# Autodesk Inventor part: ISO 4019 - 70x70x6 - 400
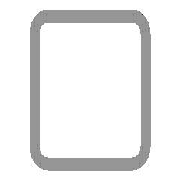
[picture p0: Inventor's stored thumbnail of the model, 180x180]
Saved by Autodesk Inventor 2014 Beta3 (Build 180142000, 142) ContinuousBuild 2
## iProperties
IsCustomPart: 1
Created: 2010-11
Part Number: ISO 4019 - 70x70x6 - 400
Material: Steel, Mild
Description: Structural steels - Cold-formed, welded, structural hollow sections
Document SubType Name: Modeling
Standard: ISO
Designer: Beta-8540w
Standard Revision: Second edition 2001-09-01
Standards Organization: ISO
Language: en-US
Size Designation: 70x70x6
Categories: <MemberInstance><Categories><Category DisplayName="Structural Shapes" InternalName="089c4875-fa83-4c05-b084-43b9cc11f5ed" Mnemonic="GRDR"><CategoryParameter Dis
Stock Number: 70x70x6
Density: 7.86 g/cm^3
Appearance: Steel
_CCFamilyMember: 28
_CCFamilyDisplayName: ISO 4019 (Square) - Structural steels - Cold-formed, welded, structural hollow sections
_FrameMemberDoc: Frame Member File
_Version: 15.0.0
_GetPNFromCC: 1
G_L: 400.000 mm
G_W: 70.000 mm
G_H: 70.000 mm
Author: Beta-8540w
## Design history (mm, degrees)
node "Start plane"
node "End plane"
sketch "Sketch"
  geometry: L1 (-35, -23)-(-35, 23); L2 (-23, 35)-(23, 35); L3 (35, 23)-(35, -23); L4 (23, -35)-(-23, -35); L5 (-23, 29)-(23, 29); L6 (29, 23)-(29, -23); L7 (23, -29)-(-23, -29); L8 (-29, -23)-(-29, 23); L9 (0, 52.479)-(0, -52.479) reference; L10 (-52.479, 0)-(52.479, 0) reference; A1 r 12 centre (-23, -23) between (-35, -23) and (-23, -35); A2 r 12 centre (23, 23) between (35, 23) and (23, 35); A3 r 12 centre (-23, 23) between (-23, 35) and (-35, 23); A4 r 12 centre (23, -23) between (23, -35) and (35, -23); A5 r 6 centre (-23, 23) between (-23, 29) and (-29, 23); A6 r 6 centre (23, 23) between (29, 23) and (23, 29); A7 r 6 centre (23, -23) between (23, -29) and (29, -23); A8 r 6 centre (-23, -23) between (-29, -23) and (-23, -29)
  constraints: 16 end point, 16 point on circle, 8 centre point, 8 tangent, 4 parallel, 3 equal radius, 2 perpendicular, 7 other
  dimensions: "d7" = 12 radius of A1 (= G_IR); "d9" = 70 distance between parallel lines of L1 L3 (= G_W); "d11" = 70 distance between parallel lines of L2 L4 (= G_H); "d12" = 6 distance between parallel lines of L3 L6 (= G_T); "d15" = 35 distance between parallel lines of L9 L3 (= 0.5 x d9); "d16" = 35 distance between parallel lines of L2 L10 (= 0.5 x d11)
extrude "Body" new body sketch "Sketch" stored distance "d3" = 400 (= G_L); taper "d4" = 0 deg
node "Driven Length"
  sketch "Sketch3"
    geometry: L1 (0, 0)-(10, 0) reference
    constraints: 2 end point, 1 horizontal
  workplane "Work Plane3"
  sketch "Sketch4"
    geometry: L1 (-2, 0)-(12, 0) reference; L2 (-2, 400)-(12, 400) reference
    dimensions: "d18" = 400 distance between parallel lines of L1 L2 (derived)
sketch "Sketch5"
  geometry: L1 (0, -46)-(0, 0) reference; C1 r 20 at (35, -23); 2 further points
  constraints: 1 centre point, 1 horizontal alignment, 1 midpoint
  dimensions: "d19" = 40 diameter of C1; "d20" = 35 distance of point (0, -23) C1.centre
extrude "Extrusion2" cut sketch "Sketch5" stored distance "d21" = 10; taper "d22" = 0 deg
sketch "Sketch6"
  geometry: L1 (400, 46)-(400, 0) reference; C1 r 17 at (365, 23); 2 further points
  constraints: 1 centre point, 1 horizontal alignment, 1 midpoint
  dimensions: "d23" = 34 diameter of C1; "d24" = 35 distance of point (400, 23) C1.centre
extrude "Extrusion3" cut sketch "Sketch6" stored distance "d25" = 10; taper "d26" = 0 deg
body "Solid1"
other parameters: "G_W" = 70 [user parameter; used in 1 equation term], "G_H" = 70 [user parameter; used in 1 equation term], "G_T" = 6 [user parameter; used in 1 equation term], "G_IR" = 12 [user parameter; used in 1 equation term], "G_L" = 400 (= d18) [user parameter; used in 1 equation term], "G_OFFSET_START" = 0 [user parameter; used in 1 equation term], "G_OFFSET_END" = 0 [user parameter; used in 1 equation term], "d13" = 0 (computed from G_OFFSET_START), "d17" = 90 deg, "MAS" = 1.13 [user parameter]
